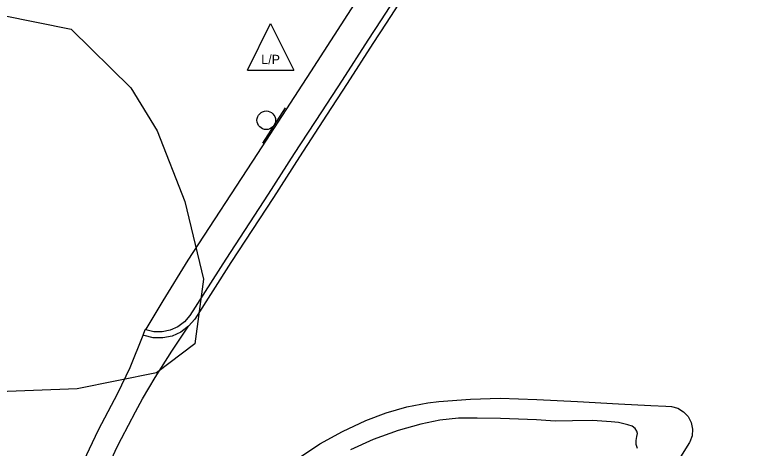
# Model space of a CAD drawing. Extents: x 2161152 to 2175754, y 602179 to 617749.
# Drawn here: x 2161857.6 to 2162017.8, y 604024.3 to 604117.6 of the extents above; entities that cross this region are included whole.
import ezdxf

# ---------------------------------------------------------------- set-up
doc = ezdxf.new("R2010")
doc.units = 0
for name, color, linetype in [('RD_EX_BldgApp_Sign', 7, 'Continuous'), ('RD_EX_Conc_Curb', 7, 'Continuous'), ('RD_EX_Conc_Gutter', 7, 'Continuous'), ('RD_EX_Conc_Sidewalk', 7, 'Continuous'), ('RD_EX_Parking_Asphalt', 7, 'Continuous'), ('RD_EX_Parking_Conc', 7, 'Continuous'), ('RD_EX_UT', 7, 'Continuous'), ('RD_EX_VEG', 7, 'Continuous')]:
    doc.layers.add(name, color=color, linetype=linetype)

msp = doc.modelspace()

# ---------------------------------------------------------------- linework, layer by layer
at = {"layer": 'RD_EX_BldgApp_Sign'}
msp.add_line((2161910.99, 604089.98), (2161915.82, 604097.57), dxfattribs=at)
msp.add_circle((2161911.7, 604094.88), 2, dxfattribs=at)
at = {"layer": 'RD_EX_Conc_Curb'}
msp.add_lwpolyline([(2161950.02, 604137.58), (2161936.42, 604116.52), (2161933.55, 604112.11), (2161928.01, 604103.53), (2161923.56, 604096.67), (2161917.73, 604087.73), (2161912.13, 604078.95), (2161903.01, 604064.96), (2161895.24, 604052.85), (2161894.09, 604051.49), (2161892.67, 604050.42), (2161891.05, 604049.69), (2161889.31, 604049.33), (2161887.53, 604049.37), (2161885.8, 604049.79), (2161885.67, 604049.84)], dxfattribs=at)
at = {"layer": 'RD_EX_Conc_Gutter'}
msp.add_lwpolyline([(2161951.12, 604136.87), (2161937.52, 604115.8), (2161934.65, 604111.39), (2161929.11, 604102.82), (2161924.65, 604095.96), (2161918.83, 604087.02), (2161913.23, 604078.25), (2161904.11, 604064.25), (2161896.3, 604052.07), (2161894.99, 604050.53), (2161893.34, 604049.29), (2161891.45, 604048.44), (2161889.43, 604048.02), (2161887.36, 604048.06), (2161885.41, 604048.54), (2161885.2, 604048.62), (2161885.67, 604049.84)], dxfattribs=at)
at = {"layer": 'RD_EX_Conc_Sidewalk'}
msp.add_lwpolyline([(2161885.85, 604049.93), (2161889.53, 604056.03), (2161894.87, 604064.78), (2161909.87, 604087.73), (2161921.27, 604105.3), (2161930.67, 604119.84), (2161942.67, 604138.13), (2161958.45, 604162.85), (2161972.76, 604184.87), (2161973.98, 604186.74), (2161981.65, 604198.54), (2161985.68, 604204.85), (2161987.67, 604207.96), (2161989.23, 604210.4), (2161992.99, 604216.27), (2162008.82, 604240.74), (2162012.59, 604246.56), (2162017.75, 604254.53), (2162012.87, 604257.89), (2162009.71, 604260.07), (2162000.75, 604266.2), (2161997.61, 604268.42)], dxfattribs=at)
at = {"layer": 'RD_EX_Parking_Asphalt'}
for points in [[(2161871.13, 604018.83), (2161875.6, 604028.22), (2161879.74, 604036.11), (2161882.4, 604041.67), (2161885.2, 604048.62)], [(2161991.6, 604024.24), (2161991.33, 604025.07), (2161991.27, 604025.93), (2161991.44, 604026.82), (2161991.57, 604027.46), (2161991.45, 604027.95), (2161991.11, 604028.51), (2161990.42, 604029.05), (2161989.51, 604029.36), (2161987.52, 604029.82), (2161985.95, 604029.99), (2161981.87, 604030.23), (2161977.61, 604030.15), (2161973.85, 604030.11), (2161969.88, 604030.38), (2161962.11, 604030.66), (2161957.08, 604030.79), (2161953.1, 604030.75), (2161949.02, 604030.34), (2161944.96, 604029.49), (2161940.12, 604028.1), (2161934.72, 604026.16), (2161929.84, 604023.96)]]:
    msp.add_lwpolyline(points, dxfattribs=at)
at = {"layer": 'RD_EX_Parking_Conc'}
for points in [[(2161877.16, 604019.25), (2161879.6, 604024.56), (2161880.53, 604026.36), (2161883.54, 604032.1), (2161885.09, 604034.89), (2161887.79, 604039.5), (2161891.41, 604045.2), (2161894.99, 604050.53)], [(2161918.62, 604022.15), (2161923.26, 604025.2), (2161928.12, 604027.92), (2161933.15, 604030.28), (2161937.5, 604031.91), (2161941.95, 604033.17), (2161946.5, 604034.03), (2161948.86, 604034.33), (2161955.67, 604034.88), (2161962, 604035.04), (2161969.93, 604034.81), (2161978.67, 604034.36), (2161987.46, 604033.88), (2161994.46, 604033.52), (2161997.67, 604033.35), (2161998.88, 604033.28), (2162000.26, 604032.89), (2162001.49, 604032.15), (2162002.47, 604031.1), (2162003.12, 604029.82), (2162003.41, 604028.42), (2162003.31, 604026.98), (2162002.82, 604025.63), (2162002.76, 604025.51), (2162000.81, 604022.41)]]:
    msp.add_lwpolyline(points, dxfattribs=at)
at = {"layer": 'RD_EX_UT'}
for p, q in [((2161907.64, 604105.68), (2161912.64, 604115.68)), ((2161912.64, 604115.68), (2161917.64, 604105.68)), ((2161907.64, 604105.68), (2161917.64, 604105.68))]:
    msp.add_line(p, q, dxfattribs=at)
at = {"layer": 'RD_EX_VEG'}
msp.add_lwpolyline([(2161839.74, 604115.12), (2161854.84, 604117.48), (2161869.71, 604114.49), (2161882.55, 604101.85), (2161888.22, 604092.58), (2161894.17, 604077.41), (2161898.19, 604060.66), (2161896.32, 604046.73), (2161888.11, 604040.51), (2161870.99, 604037.04), (2161850.32, 604036.3), (2161838.25, 604037.64), (2161830.16, 604031.84), (2161819.17, 604019.32), (2161809.7, 604010.82), (2161796.02, 604012.04), (2161786.5, 604021.64), (2161779.82, 604036.63), (2161785.76, 604051.72), (2161797.65, 604063.31), (2161807.99, 604073.47), (2161817.39, 604085.07), (2161823.93, 604096.9), (2161839.74, 604115.12)], dxfattribs=at)

# ---------------------------------------------------------------- texts
at = {"layer": 'RD_EX_UT'}
msp.add_text('L/P', height=2, dxfattribs=at).set_placement((2161910.64, 604106.97))

doc.saveas('drawing.dxf')
